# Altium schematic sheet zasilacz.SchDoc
size A4
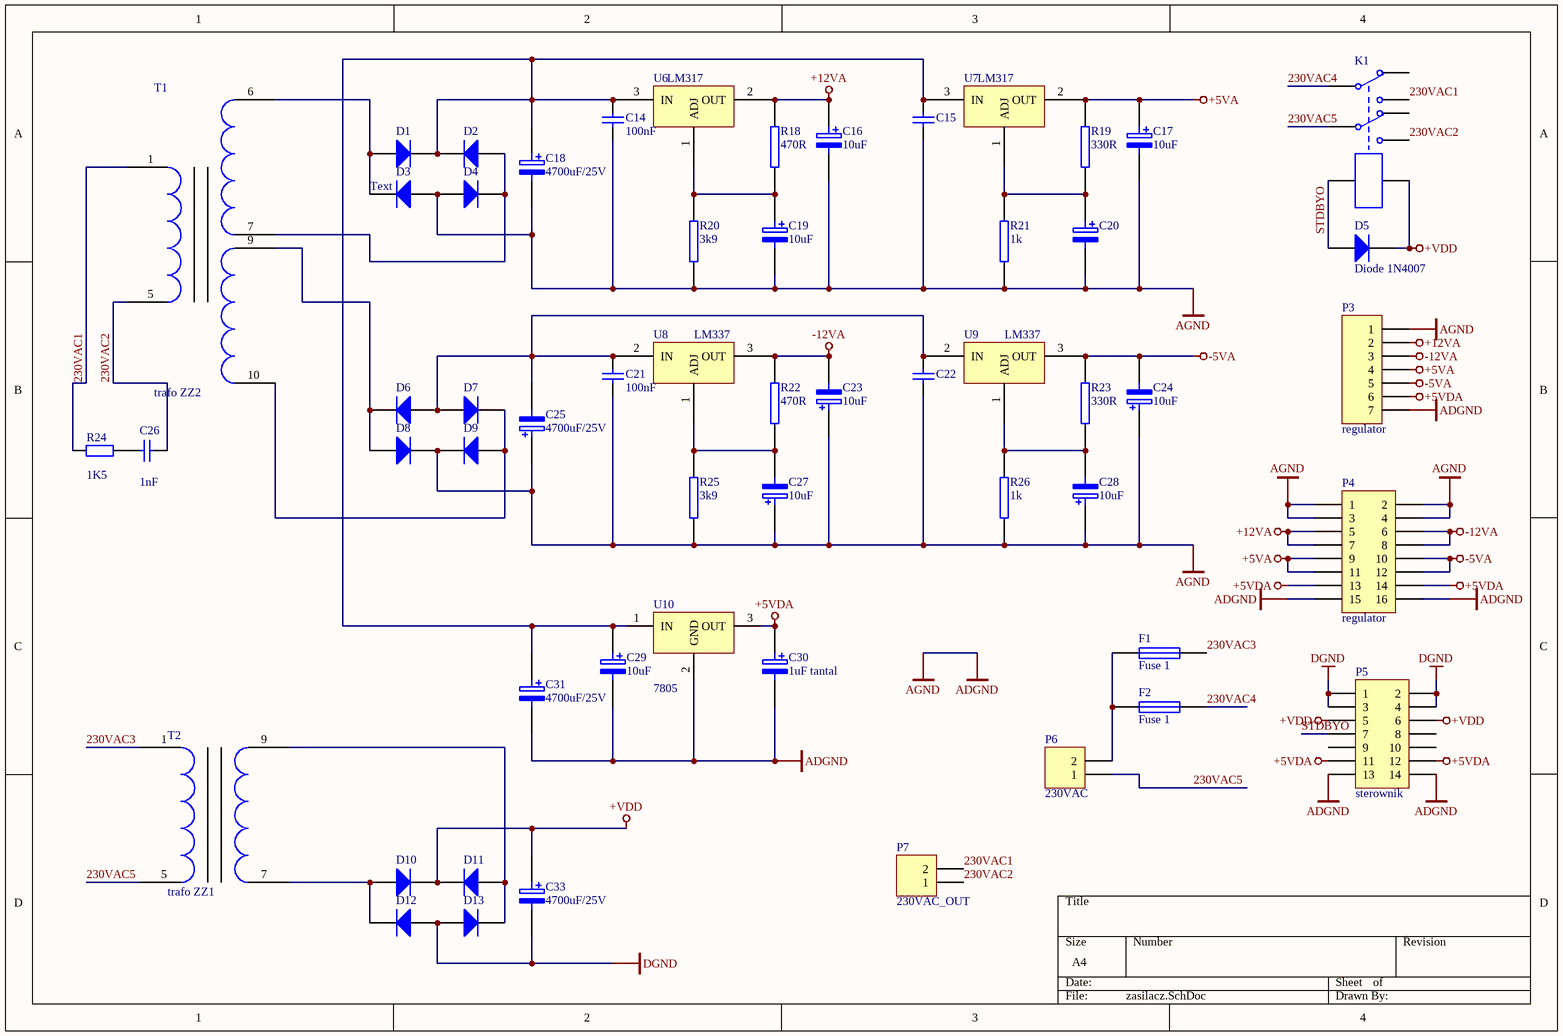
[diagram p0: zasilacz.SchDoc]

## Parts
C14  value 100nF  [1206]  (hidden comment: Cap)
C15  Cap  [1206]  (value not drawn)
C16  value 10uF  [RB.1/.2]  (hidden comment: ELECTRO2)
C17  value 10uF  [RB.1/.2]  (hidden comment: ELECTRO2)
C18  value 4700uF/25V  [RB.3/.6]  (hidden comment: ELECTRO2)
C19  value 10uF  [RB.1/.2]  (hidden comment: ELECTRO2)
C20  ELECTRO2  [RB.1/.2]  (value not drawn)
C21  value 100nF  [1206]  (hidden comment: Cap)
C22  Cap  [1206]  (value not drawn)
C23  value 10uF  [RB.1/.2]  (hidden comment: ELECTRO2)
C24  value 10uF  [RB.1/.2]  (hidden comment: ELECTRO2)
C25  value 4700uF/25V  [RB.3/.6]  (hidden comment: ELECTRO2)
C26  value 1nF  [RAD-0.3]  (hidden comment: Cap)
C27  value 10uF  [RB.1/.2]  (hidden comment: ELECTRO2)
C28  value 10uF  [RB.1/.2]  (hidden comment: ELECTRO2)
C29  value 10uF  [RB.1/.2]  (hidden comment: ELECTRO2)
C30  value 1uF tantal  [RB.1/.2]  (hidden comment: ELECTRO2)
C31  value 4700uF/25V  [RB.3/.6]  (hidden comment: ELECTRO2)
C33  value 4700uF/25V  [RB.3/.6]  (hidden comment: ELECTRO2)
D1  Diode 1N4001  [DO-41]  (value not drawn)
D2  Diode 1N4001  [DO-41]  (value not drawn)
D3  Diode 1N4001  [DO-41]  (value not drawn)
D4  Diode 1N4001  [DO-41]  (value not drawn)
D5  Diode 1N4007  [DO-41]
D6  Diode 1N4001  [DO-41]  (value not drawn)
D7  Diode 1N4001  [DO-41]  (value not drawn)
D8  Diode 1N4001  [DO-41]  (value not drawn)
D9  Diode 1N4001  [DO-41]  (value not drawn)
D10  Diode 1N4001  [DO-41]  (value not drawn)
D11  Diode 1N4001  [DO-41]  (value not drawn)
D12  Diode 1N4001  [DO-41]  (value not drawn)
D13  Diode 1N4001  [DO-41]  (value not drawn)
F1  Fuse 1  [BEZP_OKR]
F2  Fuse 1  [BEZP_OKR]
K1  Relay-DPDT  [Prz_big]  (value not drawn)
P3  regulator  [SIP7]
P4  regulator  [HDR2X8]
P5  sterownik  [HDR2X7]
P6  230VAC  [ZLSRUB2-1]
P7  230VAC_OUT  [ZLSRUB2-1]
R18  value 470R  [AXIAL0.4]  (hidden comment: RES2)
R19  value 330R  [AXIAL0.4]  (hidden comment: RES2)
R20  value 3k9  [AXIAL0.4]  (hidden comment: RES2)
R21  value 1k  [AXIAL0.4]  (hidden comment: RES2)
R22  value 470R  [AXIAL0.4]  (hidden comment: RES2)
R23  value 330R  [AXIAL0.4]  (hidden comment: RES2)
R24  value 1K5  [AXIAL-0.4]  (hidden comment: Res2)
R25  value 3k9  [AXIAL0.4]  (hidden comment: RES2)
R26  value 1k  [AXIAL0.4]  (hidden comment: RES2)
T1  trafo ZZ2  [TRAFO ZZ7]
T2  trafo ZZ1  [TRAFO ZZ7]
U6  LM317  [78XXST]
U7  LM317  [78XXST]
U8  LM337  [78XXST]
U9  LM337  [78XXST]
U10  7805  [78XXST]

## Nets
+5VA: C17.1 P3.4 P4.9 P4.11 R19.1 U7.2(OUT)
+5VDA: C30.1 P3.6 P4.13 P4.14 P5.11 P5.12 U10.3(OUT)
+12VA: C16.1 P3.2 P4.5 P4.7 R18.1 U6.2(OUT)
+VDD: C33.1 D5.2(K) D10.2(K) D11.2(K) K1.8 P5.5 P5.6
-5VA: C24.2 P3.5 P4.10 P4.12 R23.1 U9.3(OUT)
-12VA: C23.2 P3.3 P4.6 P4.8 R22.1 U8.3(OUT)
ADGND: C14.2 C15.2 C16.2 C17.2 C18.2 C19.2 C20.2 C21.2 C22.2 C23.1 C24.1 C25.1 C27.1 C28.1 C29.2 C30.2 C31.2 D3.1(A) D4.1(A) D8.2(K) D9.2(K) P3.1 P3.7 P4.1 P4.2 P4.3 P4.4 P4.15 P4.16 P5.13 P5.14 R20.2 R21.2 R25.2 R26.2 U10.2(GND)  [also labelled AGND]
DGND: C33.2 D12.1(A) D13.1(A) P5.1 P5.2 P5.3 P5.4
230VAC1: K1.3 P7.2 R24.1 T1.1
230VAC2: C26.2 K1.6 P7.1 T1.5
230VAC3: F1.2 T2.1
230VAC4: F2.2 K1.1
230VAC5: K1.4 P6.1 T2.5
STDBYO: D5.1(A) K1.7 P5.7
NetC14_1: C14.1 C15.1 C18.1 C29.1 C31.1 D1.2(K) D2.2(K) U6.3(IN) U7.3(IN) U10.1(IN)
NetC19_1: C19.1 R18.2 R20.1 U6.1(ADJ)
NetC20_1: C20.1 R19.2 R21.1 U7.1(ADJ)
NetC21_1: C21.1 C22.1 C25.2 D6.1(A) D7.1(A) U8.2(IN) U9.2(IN)
NetC26_1: C26.1 R24.2
NetC27_2: C27.2 R22.2 R25.1 U8.1(ADJ)
NetC28_2: C28.2 R23.2 R26.1 U9.1(ADJ)
NetD1_1: D1.1(A) D3.2(K) T1.6
NetD2_1: D2.1(A) D4.2(K) T1.7
NetD6_2: D6.2(K) D8.1(A) T1.9
NetD7_2: D7.2(K) D9.1(A) T1.10
NetD10_1: D10.1(A) D12.2(K) T2.7
NetD11_1: D11.1(A) D13.2(K) T2.9
NetF1_1: F1.1 F2.1 P6.2

Not connected (* = marked no-connect by the designer): K1 2 5; P5 8 9 10

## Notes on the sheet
- (near D3) Text

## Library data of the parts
C14 C21 C26 = Cap: Capacitor
C15 C22 = Cap: Capacitor; Value: 100pF
C16-C20 C23-C25 C27-C31 C33 = ELECTRO2: Electrolytic Capacitor
D1-D4 D6-D13 = Diode 1N4001: 1 Amp General Purpose Rectifier
D5 = Diode 1N4007: 1 Amp General Purpose Rectifier
F1 F2 = Fuse 1: Fuse
K1 = Relay-DPDT: Dual-Pole Dual-Throw Relay
P3 = MHDR1X7: Header, 7-Pin
P4 = Header 8X2: Header, 8-Pin, Dual row
P5 = Header 7X2: Header, 7-Pin, Dual row
P6 P7 = Header 2: Header, 2-Pin
R24 = Res2: Resistor
U10 = 78XX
